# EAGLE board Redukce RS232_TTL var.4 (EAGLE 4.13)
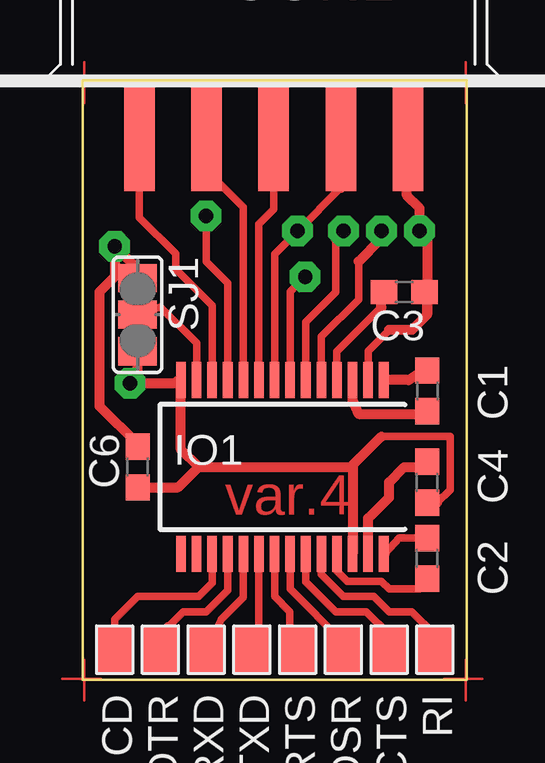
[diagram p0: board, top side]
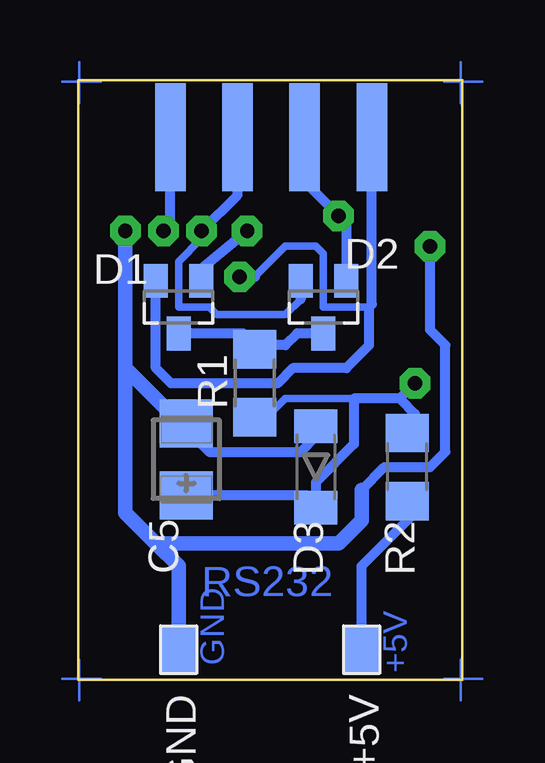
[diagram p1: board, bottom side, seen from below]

Size 16 x 25 mm. Coordinates in mm from the lower left corner, seen from the top.
Outline: 0,0 0,25 16,25 16,0 0,0
Copper layers (1*16): Top 0.035mm / dielectric 1.5mm / Bottom 0.035mm
Design rules "default": minimum track width 10mil, minimum drill 24mil, track to track 8mil, track to pad 8mil, pad to pad 8mil, via to via 8mil, smd to smd 8mil, copper to edge 40mil, drill to drill 8mil, minimum pad ring 10mil, minimum via ring 8mil, stop-mask expansion 0mil, vias tented up to drill 0mil, thermal gap 10mil

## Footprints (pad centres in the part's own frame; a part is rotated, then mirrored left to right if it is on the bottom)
TP20X15 = smd 1.5 x 2: TP 0,0
C0603 = smd 1.1 x 1: 1 -0.85,0; 2 0.85,0
CT3528 = smd 2 x 2.2: 1 -1.5,0; 2 1.5,0
CAN9MSMD = smd 1.27 x 4.5: 1 -5.6,-1.4; 2 -2.8,-1.4; 3 0,-1.4; 4 2.8,-1.4; 5 5.6,-1.4 | smd 1.27 x 4.5 bottom: 6 -4.2,-1.4; 7 -1.4,-1.4; 8 1.4,-1.4; 9 4.2,-1.4
SOT23 = smd 1 x 1.4: 1 -0.95,-1.1; 2 0.95,-1.1; 3 0,1.1
MLL-34 = smd 1.4 x 1.8: 1 -1.7,0; 2 1.7,0
SSOP28 = smd 0.4 x 1.5: 1 -4.225,-3.625; 2 -3.575,-3.625; 3 -2.925,-3.625; 4 -2.275,-3.625; 5 -1.625,-3.625; 6 -0.975,-3.625; 7 -0.325,-3.625; 8 0.325,-3.625; 9 0.975,-3.625; 10 1.625,-3.625; 11 2.275,-3.625; 12 2.925,-3.625; 13 3.575,-3.625; 14 4.225,-3.625; 15 4.225,3.625; 16 3.575,3.625; 17 2.925,3.625; 18 2.275,3.625; 19 1.625,3.625; 20 0.975,3.625; 21 0.325,3.625; 22 -0.325,3.625; 23 -0.975,3.625; 24 -1.625,3.625; 25 -2.275,3.625; 26 -2.925,3.625; 27 -3.575,3.625; 28 -4.225,3.625
R1206 = smd 1.6 x 1.803: 1 -1.422,0; 2 1.422,0
SJ_2 = smd 1.168 x 1.6: 1 -1.524,0; 2 0,0; 3 1.524,0

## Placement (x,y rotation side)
+5V  TPTP15X20  [TP20X15]  4.19,1.25 180 bottom
C1  100nF/16V  [C0603]  14.35,12.05 270 top
C2  100nF/16V  [C0603]  14.35,5.06 90 top
C3  100nF/16V  [C0603]  13.4,16.18 180 top
C4  100nF/16V  [C0603]  14.35,8.24 90 top
C5  10uF/6V  [CT3528]  11.49,9.19 90 bottom
C6  100nF/16V  [C0603]  2.29,8.87 90 top
CD  TPTP15X20  [TP20X15]  1.33,1.25 180 top
CON1  CAN 9 SAMICE  [CAN9MSMD]  7.96,24.03 0 top
CTS  TPTP15X20  [TP20X15]  12.76,1.25 180 top
D1  BAT54C  [SOT23]  11.81,15.54 180 bottom
D2  BAT54C  [SOT23]  5.78,15.54 180 bottom
D3  5V1  [MLL-34]  6.09,8.87 90 bottom
DSR  TPTP15X20  [TP20X15]  10.86,1.25 180 top
DTR  TPTP15X20  [TP20X15]  3.24,1.25 180 top
GND  TPTP15X20  [TP20X15]  11.81,1.25 180 bottom
IO1  MAX3238  [SSOP28]  8.32,8.87 180 top
R1  22R  [R1206]  8.63,12.37 270 bottom
R2  22R  [R1206]  2.29,8.87 270 bottom
RI  TPTP15X20  [TP20X15]  14.67,1.25 180 top
RTS  TPTP15X20  [TP20X15]  8.95,1.25 180 top
RXD  TPTP15X20  [TP20X15]  5.14,1.25 180 top
SJ1  [SJ_2]  2.29,15.22 270 top
TXD  TPTP15X20  [TP20X15]  7.05,1.25 180 top

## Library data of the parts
+5V CD CTS DSR DTR GND RI RTS RXD TXD = testpad
C1-C4 C6 R1 = rcl
C5 D3 R2 = IPC-RCL
CON1 = RADEK
D1 D2 = diode
IO1 = max3238
SJ1 = jumper

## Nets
+5V: C4.1 C5.1 C6.1 D3.1 IO1.14 IO1.26 R1.2 R2.1 SJ1.3
CD: CON1.1 IO1.12
CTS: CON1.8 D2.2 IO1.6
DSR: CON1.6 D1.2 IO1.7
DTR: CON1.7 D2.1 IO1.11
GND: C3.1 C5.2 C6.2 CON1.5 D3.2 GND.TP IO1.2 SJ1.1
N$1: C4.2 IO1.27
N$2: C3.2 IO1.4
N$3: DTR.TP IO1.18
N$4: IO1.20 TXD.TP
N$5: C2.1 IO1.25
N$6: C2.2 IO1.28
N$7: C1.2 IO1.3
N$8: C1.1 IO1.1
N$9: IO1.21 RTS.TP
N$10: CD.TP IO1.17
N$11: D1.3 D2.3 R1.1
N$12: IO1.19 RXD.TP
N$13: DSR.TP IO1.22
N$14: CTS.TP IO1.23
N$15: IO1.24 RI.TP
N$16: +5V.TP R2.2
N$17: IO1.13 SJ1.2
RI: CON1.9 IO1.5
RTS: CON1.4 D1.1 IO1.8
RXD: CON1.2 IO1.10
TXD: CON1.3 IO1.9

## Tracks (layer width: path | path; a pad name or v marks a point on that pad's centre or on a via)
+5V  (via drill 0.6 pad 1.27)
  Top 0.305: 14.77,7.39 15.3,7.92 15.3,10.14 12.45,10.14
  Top 0.406: 14.77,7.39 C4.1 | 12.45,10.14 11.18,8.87 10.86,8.87 | 4.83,8.87 4.09,9.61 IO1.14 4,12.5 3.87,12.37 2.29,12.37 | 4.83,8.87 10.86,8.87 | IO1.26 11.24,8.87 10.86,8.87 | 2.29,12.37 v1.97,12.37 | 2.29,12.37 SJ1.3 | C6.1 3.98,8.02 4.83,8.87
  Bottom 0.305: 8.15,10.94 7.37,11.73 4.51,11.73
  Bottom 0.406: 8.15,10.94 R1.2 | 2.6,11.73 4.51,11.73 4.51,9.82 6.09,8.24 6.09,7.29 | v1.97,12.37 2.6,11.73 | 6.09,7.29 D3.1 | C5.1 6.5,7.69 6.09,7.29 | R2.1 1.97,11.1 2.6,11.73
CD
  Top 0.305: IO1.12 5.39,15.61 3.87,17.13 3.87,17.76 2.36,19.28 CON1.1
CTS  (via drill 0.6 pad 1.27)
  Top 0.305: IO1.6 9.29,14.93 10.54,16.17 10.54,18.4
  Top 0.406: v10.86,18.72 10.54,18.4
  Bottom 0.305: 6.73,15.86 7.37,15.22 10.22,15.22 10.54,15.54 11.81,15.54 11.81,17.44 10.86,18.4
  Bottom 0.406: CON1.8 9.36,20.22 v10.86,18.72 10.86,18.4 | D2.2 6.73,15.86
DSR  (via drill 0.6 pad 1.27)
  Top 0.305: IO1.7 8.64,16.18 v9.27,16.81
  Bottom 0.305: 3.87,15.54 5.78,15.54 5.78,17.76 6.09,18.08 7.37,18.08 8.63,16.81
  Bottom 0.406: D1.2 12.76,13 12.13,12.37 7.68,12.37 7.05,13 4.83,13 3.87,13.95 3.87,15.54 3.76,15.66 CON1.6 | 8.63,16.81 v9.27,16.81
DTR  (via drill 0.6 pad 1.27)
  Top 0.305: v5.14,19.35 5.14,17.44 6.04,16.54 IO1.11
  Bottom 0.406: CON1.7 6.56,20.76 v5.14,19.35 4.83,19.03 D2.1
GND  (via drill 0.6 pad 1.27)
  Top 0.305: IO1.2 11.89,13.72 12.76,14.59
  Top 0.406: CON1.5 13.51,22.63 13.51,20.19 14.03,19.67 v14.03,18.72 14.35,18.4 14.35,15.22 | 12.76,14.59 13.71,14.59 14.35,15.22 | C3.1 14.35,16.17 14.35,15.22 | SJ1.1 2.29,17.13 v1.33,18.08 1.33,16.81 0.7,16.17 0.7,11.41 2.29,9.82 C6.2
  Bottom 0.406: D3.2 6.09,10.14 6.73,9.51 10.54,9.51 11.49,10.46 C5.2 11.72,10.69 | v1.33,18.08 1.33,14.59 0.7,13.95 0.7,9.51 1.33,8.87 3.24,8.87 4.19,7.92
  Bottom 0.61: 14.03,13 11.72,10.69 | 14.03,13 v14.03,18.72 | GND.TP 11.81,4.75 12.76,5.7 | 12.76,5.7 14.03,6.97 14.03,13 | 4.19,7.92 4.19,6.65 5.14,5.7 12.76,5.7
N$1
  Top 0.406: IO1.27 11.89,6.73 12.76,7.6 12.76,8.24 13.4,8.87 14.35,8.87 C4.2
N$2
  Top 0.305: IO1.4 10.59,13.69 12.45,15.54
  Top 0.406: C3.2 12.45,16.17 12.45,15.54
N$3
  Top 0.305: IO1.18 6.04,3.74 5.14,2.84 4.19,2.84 3.56,2.21
  Top 0.406: DTR.TP 3.56,2.21
N$4
  Top 0.305: 7.34,1.91 IO1.20
  Top 0.406: TXD.TP 7.34,1.91
N$5
  Top 0.305: IO1.25 10.59,4.53 11.02,4.11 12.45,4.11 12.76,3.79 14.03,3.79 14.35,4.11
  Top 0.406: 14.35,4.11 C2.1
N$6
  Top 0.305: C2.2 13.18,5.91 12.58,5.25
  Top 0.406: 12.58,5.25 IO1.28
N$7
  Top 0.406: IO1.3 11.24,11.66 11.49,11.1 14.03,11.1 C1.2
N$8
  Top 0.406: C1.1 14.35,13 13.58,12.5 IO1.1
N$9
  Top 0.305: IO1.21 7.99,3.48 8.63,2.84 8.63,2.21
  Top 0.406: 8.63,2.21 9.27,1.57 RTS.TP
N$10
  Top 0.305: IO1.17 5.39,4.04 4.83,3.48 2.29,3.48 1.33,2.52 CD.TP
N$11
  Bottom 0.406: D2.3 6.88,14.44 7.37,13.95 8.63,13.95 | 8.63,13.95 R1.1 | D1.3 9.12,14.44 8.63,13.95
N$12
  Top 0.305: IO1.19 6.69,3.44 5.78,2.52 RXD.TP
N$13
  Top 0.305: IO1.22 8.64,3.79 10.86,1.57
  Top 0.406: DSR.TP 10.86,1.57
N$14
  Top 0.305: IO1.23 9.29,4.09 10.54,2.84 11.81,2.84 12.76,1.89
  Top 0.406: CTS.TP 13.08,1.25 12.76,1.57 12.76,1.89
N$15
  Top 0.305: IO1.24 9.94,4.39 10.86,3.48 12.13,3.48 12.76,2.84 13.71,2.84 14.67,1.89
  Top 0.406: 14.67,1.89 RI.TP
N$16
  Bottom 0.406: R2.2 1.97,6.97 4.19,4.75 +5V.TP
N$17
  Top 0.305: IO1.13 4.74,14.04 3.24,15.54 SJ1.2
N$18
  Bottom 0.1: 0.05,24.04 0.05,25.74
N$26
  Bottom 0.1: 0.75,24.94 -0.85,24.94
N$27
  Top 0.1: 0.75,24.94 -0.85,24.94
N$28
  Top 0.1: 0.05,24.04 0.05,25.74
N$29
  Bottom 0.1: 15.95,24.04 15.95,25.74
N$30
  Bottom 0.1: 16.65,24.94 15.05,24.94
N$31
  Top 0.1: 16.65,24.94 15.05,24.94
N$32
  Top 0.1: 15.95,24.04 15.95,25.74
N$33
  Bottom 0.1: 0.05,-0.86 0.05,0.85
N$34
  Bottom 0.1: 0.75,0.04 -0.85,0.04
N$35
  Top 0.1: 0.75,0.04 -0.85,0.04
N$36
  Top 0.1: 0.05,-0.86 0.05,0.85
N$37
  Bottom 0.1: 15.95,-0.86 15.95,0.85
N$38
  Bottom 0.1: 16.65,0.04 15.05,0.04
N$39
  Top 0.1: 16.65,0.04 15.05,0.04
N$40
  Top 0.1: 15.95,-0.86 15.95,0.85
RI  (via drill 0.6 pad 1.27)
  Top 0.305: IO1.5 9.94,14.31 11.49,15.86 11.49,17.44
  Top 0.406: v12.45,18.72 12.45,18.4 11.49,17.44
  Bottom 0.406: CON1.9 12.16,18.74 v12.45,18.72
RTS  (via drill 0.6 pad 1.27)
  Top 0.305: IO1.8 7.99,17.76 v8.95,18.72 10.76,20.52
  Top 0.406: 10.76,20.52 CON1.4
  Bottom 0.406: D1.1 10.86,17.12 v8.95,18.72
RXD
  Top 0.305: IO1.10 6.69,19.71 5.14,21.26
  Top 0.406: CON1.2 5.16,22.54 5.14,22.53 5.14,21.26
TXD
  Top 0.305: IO1.9 7.34,19.01 7.96,19.62 CON1.3

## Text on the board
Top: var.4
Bottom: RS232 | GND | +5V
